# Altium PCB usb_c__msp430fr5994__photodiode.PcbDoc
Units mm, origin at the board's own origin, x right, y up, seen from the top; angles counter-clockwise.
Board outline 56 x 30 mm, 2 copper layers (Top, Bottom), stack 0 mm thick; 27 components, 18 nets, 155 pads, 48 vias.
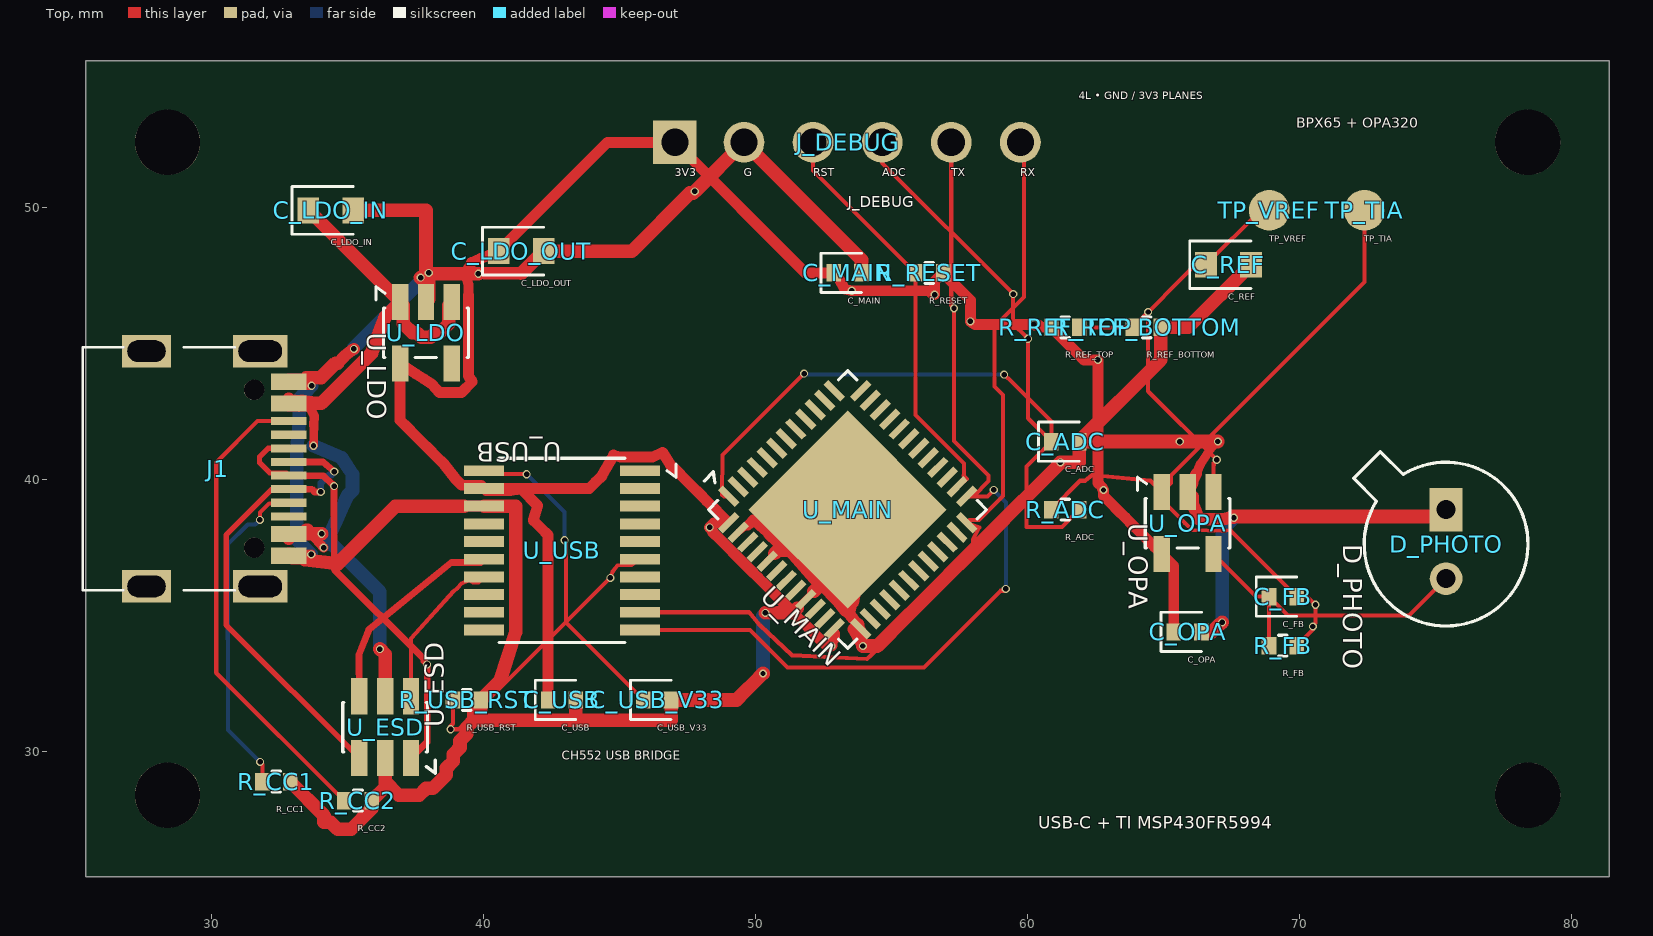
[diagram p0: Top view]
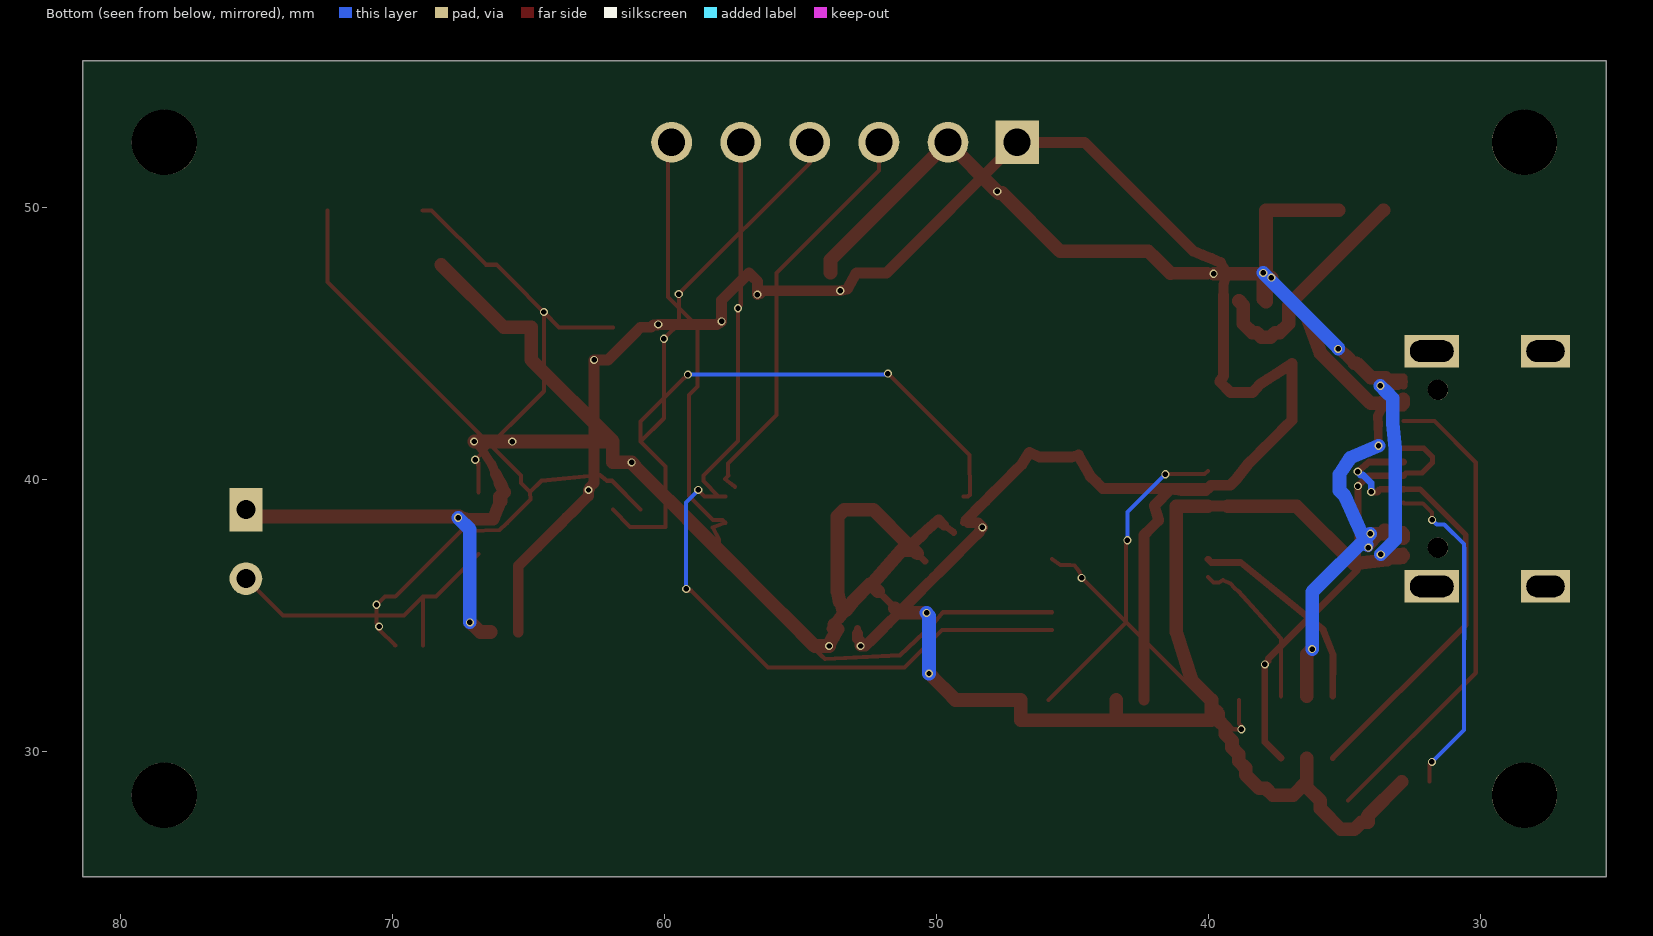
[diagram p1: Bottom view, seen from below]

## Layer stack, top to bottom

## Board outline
25.4,55.4 81.4,55.4 81.4,25.4 25.4,25.4

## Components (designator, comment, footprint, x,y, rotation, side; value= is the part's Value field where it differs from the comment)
C_ADC "" TSCIRCUIT-1.5600x0.6400mm 61.4,41.4 r0 top
C_FB "" TSCIRCUIT-1.5600x0.6400mm 69.4,35.7 r0 top
C_LDO_IN "" TSCIRCUIT-2.4500x0.9500mm 34.4,49.9 r0 top
C_LDO_OUT "" TSCIRCUIT-2.4500x0.9500mm 41.4,48.4 r0 top
C_MAIN "" TSCIRCUIT-1.5600x0.6400mm 53.4,47.6 r0 top
C_OPA "" TSCIRCUIT-1.5600x0.6400mm 65.9,34.4 r0 top
C_REF "" TSCIRCUIT-2.4500x0.9500mm 67.4,47.9 r0 top
C_USB "" TSCIRCUIT-1.5600x0.6400mm 42.9,31.9 r0 top
C_USB_V33 "" TSCIRCUIT-1.5600x0.6400mm 46.4,31.9 r0 top
D_PHOTO "" TSCIRCUIT-1.2000x3.9400mm 75.4,37.73 r270 top
J1 "" TSCIRCUIT-6.7732x9.8502mm 30.113,40.4 r90 top
J_DEBUG "" TSCIRCUIT-14.2000x1.5000mm 53.4,52.4 r0 top
R_ADC "" TSCIRCUIT-1.5600x0.6400mm 61.4,38.9 r0 top
R_CC1 "" TSCIRCUIT-1.5600x0.6400mm 32.4,28.9 r0 top
R_CC2 "" TSCIRCUIT-1.5600x0.6400mm 35.4,28.2 r0 top
R_FB "" TSCIRCUIT-1.5600x0.6400mm 69.4,33.9 r0 top
R_REF_BOTTOM "" TSCIRCUIT-1.5600x0.6400mm 64.4,45.6 r0 top
R_REF_TOP "" TSCIRCUIT-1.5600x0.6400mm 61.4,45.6 r0 top
R_RESET "" TSCIRCUIT-1.5600x0.6400mm 56.4,47.6 r0 top
R_USB_RST "" TSCIRCUIT-1.5600x0.6400mm 39.4,31.9 r0 top
TP_TIA "" TSCIRCUIT-1.5000x1.5000mm 72.4,49.9 r0 top
TP_VREF "" TSCIRCUIT-1.5000x1.5000mm 68.9,49.9 r0 top
U_ESD "" TSCIRCUIT-2.5000x3.6000mm#1 36.4,30.9 r90 top
U_LDO "" TSCIRCUIT-2.5000x3.6000mm#2 37.9,45.4 r270 top
U_MAIN "" TSCIRCUIT-9.5459x9.5459mm 53.4,38.9 r315 top
U_OPA "" TSCIRCUIT-2.5000x3.6000mm#2 65.9,38.4 r270 top
U_USB "" TSCIRCUIT-7.2000x6.2500mm 42.9,37.4 r180 top

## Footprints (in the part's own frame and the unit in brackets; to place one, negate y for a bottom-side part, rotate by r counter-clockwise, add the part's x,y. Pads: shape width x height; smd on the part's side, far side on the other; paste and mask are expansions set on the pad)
TSCIRCUIT-1.2000x3.9400mm [mm]
  rect 1.6x1.2 hole 0.7: 1(-1.17,0)
  round 1.2 hole 0.7: 2(1.37,0)
  silkscreen extent -3.3,-3.4 3.11,3.01
TSCIRCUIT-1.5000x1.5000mm [mm]
  round 1.5 smd: 1(0,0)
TSCIRCUIT-1.5600x0.6400mm [mm]
  rect 0.54x0.64 smd: 1(-0.51,0) 2(0.51,0)
  silkscreen extent -0.98,-0.72 0.51,0.72
TSCIRCUIT-2.4500x0.9500mm [mm]
  rect 0.8x0.95 smd: 1(-0.825,0) 2(0.825,0)
  silkscreen extent -1.43,-0.87 0.82,0.87
TSCIRCUIT-2.5000x3.6000mm#1 [mm]
  rect 1.325x0.6 smd: 1(-1.137,-0.95) 2(-1.137,0) 3(-1.137,0.95) 4(1.138,0.95) 5(1.138,0) 6(1.138,-0.95)
  silkscreen extent -1.69,-1.84 0.91,1.56
TSCIRCUIT-2.5000x3.6000mm#2 [mm]
  rect 1.325x0.6 smd: 1(-1.137,-0.95) 2(-1.137,0) 3(-1.137,0.95) 4(1.138,0.95) 5(1.138,-0.95)
  silkscreen extent -1.69,-1.84 0.91,1.56
TSCIRCUIT-6.7732x9.8502mm [mm]
  rect 1.2x2 hole 0.8 slot 1.6 at 90 deg: 1(-4.325,-1.693) 1(4.325,-1.693)
  rect 1.2x1.8 hole 0.8 slot 1.4 at 90 deg: 1(-4.325,2.487) 1(4.325,2.487)
  rect 0.3x1.3 smd: 1(-3.35,-2.737) 2(-3.05,-2.737) 3(-2.55,-2.737) 4(-2.25,-2.737) 5(-1.75,-2.737) 6(-1.25,-2.737) 7(-0.75,-2.737) 8(-0.25,-2.737) 9(0.25,-2.737) 10(0.75,-2.737) 11(1.25,-2.737) 12(1.75,-2.737) 13(2.55,-2.737) 14(2.25,-2.737) 15(3.35,-2.737) 16(3.05,-2.737)
  round 0.75 hole 0.75 unplated: NPTH-1(-2.9,-1.468) NPTH-2(2.9,-1.468)
  silkscreen extent -4.47,-0.75 4.47,4.83
TSCIRCUIT-7.2000x6.2500mm [mm]
  rect 1.475x0.4 smd: 1(-2.862,-2.925) 2(-2.862,-2.275) 3(-2.862,-1.625) 4(-2.862,-0.975) 5(-2.862,-0.325) 6(-2.862,0.325) 7(-2.862,0.975) 8(-2.862,1.625) 9(-2.862,2.275) 10(-2.862,2.925) 11(2.863,2.925) 12(2.863,2.275) 13(2.863,1.625) 14(2.863,0.975) 15(2.863,0.325) 16(2.863,-0.325) 17(2.863,-0.975) 18(2.863,-1.625) 19(2.863,-2.275) 20(2.863,-2.925)
  silkscreen extent -4.19,-3.39 2.31,3.38
TSCIRCUIT-9.5459x9.5459mm [mm]
  rect 0.875x0.25 smd: 1(-3.438,-2.75) 2(-3.438,-2.25) 3(-3.437,-1.75) 4(-3.437,-1.25) 5(-3.438,-0.75) 6(-3.438,-0.25) 7(-3.437,0.25) 8(-3.437,0.75) 9(-3.438,1.25) 10(-3.438,1.75) 11(-3.437,2.25) 12(-3.437,2.75) 25(3.438,2.75) 26(3.438,2.25) 27(3.438,1.75) 28(3.438,1.25) 29(3.438,0.75) 30(3.438,0.25) 31(3.438,-0.25) 32(3.438,-0.75) 33(3.438,-1.25) 34(3.438,-1.75) 35(3.438,-2.25) 36(3.438,-2.75)
  rect 0.25x0.875 smd: 13(-2.75,3.437) 14(-2.25,3.437) 15(-1.75,3.438) 16(-1.25,3.438) 17(-0.75,3.437) 18(-0.25,3.437) 19(0.25,3.438) 20(0.75,3.438) 21(1.25,3.437) 22(1.75,3.437) 23(2.25,3.438) 24(2.75,3.438) 37(2.75,-3.438) 38(2.25,-3.438) 39(1.75,-3.438) 40(1.25,-3.438) 41(0.75,-3.438) 42(0.25,-3.438) 43(-0.25,-3.438) 44(-0.75,-3.438) 45(-1.25,-3.438) 46(-1.75,-3.438) 47(-2.25,-3.438) 48(-2.75,-3.438)
  rect 5.15x5.15 smd: 49(0,0)
  silkscreen extent -4.47,-3.61 3.61,3.61
TSCIRCUIT-14.2000x1.5000mm [mm]
  rect 1.6x1.6 hole 1: 1(-6.35,0)
  round 1.5 hole 1: 2(-3.81,0) 3(-1.27,0) 4(1.27,0) 5(3.81,0) 6(6.35,0)

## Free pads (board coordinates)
  round 2.4 hole 2.4 unplated: NPTH-3(28.4,28.4) NPTH-4(78.4,52.4) NPTH-5(78.4,28.4) NPTH-6(28.4,52.4)

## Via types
v1: diameter 0.3, hole 0.2, Top to Bottom, 48 vias

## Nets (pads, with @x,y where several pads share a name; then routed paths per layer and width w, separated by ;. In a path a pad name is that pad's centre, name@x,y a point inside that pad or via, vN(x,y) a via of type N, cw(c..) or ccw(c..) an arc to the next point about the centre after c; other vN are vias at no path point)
ADC_IN: C_ADC.1 J_DEBUG.4 R_ADC.2 U_MAIN.1 | length 35.8
  Top w0.15: U_MAIN.1 48.855,39.386 48.788,39.441 48.793,40.9 v1(51.8,43.9) ; J_DEBUG.4 54.67,51.648 59.442,46.877 59.442,46.865 v1(59.487,46.82) 59.487,45.726 59.95,45.263 v1(60.034,45.179) 60.034,42.256 C_ADC.1 ; v1(59.153,43.862) 59.279,43.736 59.287,43.736 60.89,42.133 C_ADC.1 ; R_ADC.2 61.274,38.264 59.976,38.264 59.976,40.486 C_ADC.1
  Bottom w0.15: v1(51.8,43.9) 51.838,43.862 51.903,43.862 v1(59.153,43.862)
GND: C_ADC.2 C_LDO_IN.2 C_LDO_OUT.2 C_MAIN.2 C_OPA.2 C_REF.2 C_USB.2 C_USB_V33.2 D_PHOTO.1 J1.1@32.849,37.05 J1.2 J1.15 J1.16 J_DEBUG.2 R_CC1.2 R_CC2.2 R_REF_BOTTOM.2 R_USB_RST.2 U_ESD.2 U_LDO.2 U_MAIN.36 U_MAIN.40 U_MAIN.44 U_MAIN.47 U_MAIN.49 U_OPA.2 U_USB.18 | length 156.9
  Top w0.25: U_MAIN.47 49.735,38.323 ; U_MAIN.40@51.544,35.276 U_MAIN.40 ; U_MAIN.40 52.163,35.895 U_MAIN.40 ; U_MAIN.44 50.748,37.309 U_MAIN.44
  Top w0.251: U_MAIN.44 U_MAIN.44@50.716,37.278
  Top w0.288: J1.16@32.849,43.6 J1.16 32.946,43.468 J1.16@33.037,43.45
  Top w0.3: J1.1@32.849,37.05 32.849,37.2 J1.2 ; J1.16@32.849,43.6 J1.15 33.499,43.75 ; J1.2@32.864,37.323 J1.2 ; J1.1@32.911,37.2 J1.2 ; J1.16@33.13,43.45 33.224,43.45 v1(33.697,43.449)
  Top w0.301: J1.16@33.037,43.45 J1.16@33.13,43.45
  Top w0.325: J1.1@32.911,37.2 J1.1@32.975,37.043 ; v1(39.828,47.571) 39.845,47.588 40.062,47.588 ; 66.369,40.556 66.552,40.841 66.734,41.125 v1(67.013,41.401)
  Top w0.335: J1.1@32.975,37.043 J1.1@33.454,37.056
  Top w0.344: U_MAIN.36@53.613,34.865 U_MAIN.36
  Top w0.35: J1.2@32.864,37.323 33.274,37.288 v1(33.684,37.254) ; 66.212,40.217 66.369,40.556
  Top w0.375: 49.735,38.323 49.758,38.34 49.931,38.525
  Top w0.382: 53.627,34.884 U_MAIN.36@53.775,34.681
  Top w0.4: U_USB.18@39.3,39.025 U_USB.18 ; 49.931,38.525 50.143,38.342 50.355,38.158 50.546,37.963 ; 53.341,35.206 U_MAIN.36@53.613,34.865 ; U_MAIN.49@53.565,35.487 53.478,35.087 53.627,34.884
  Top w0.425: U_OPA.2@66.056,39.877 66.212,40.217
  Top w0.437: 34.652,44.284 34.914,44.546 v1(35.251,44.808) ; 50.546,37.963 50.77,37.759 50.994,37.556
  Top w0.45: 40.062,47.588 40.512,47.588 40.962,47.588 41.413,47.588 ; U_OPA.2@66.035,39.205 66.171,38.873 66.306,38.541 ; U_OPA.2@66.072,39.169 66.189,38.855 66.306,38.541 ; v1@67.567,38.645 67.181,38.541 ; v1(67.6,38.6) 67.181,38.541 ; 66.306,38.541 66.744,38.541 ; 66.306,38.541 66.744,38.541 ; 66.744,38.541 67.181,38.541 ; 66.744,38.541 67.181,38.541
  Top w0.475: U_MAIN.44@50.716,37.278 50.994,37.556 ; 53.651,34.506 U_MAIN.36@53.775,34.681 ; U_OPA.2 U_OPA.2@66.056,39.877
  Top w0.5: R_CC1.2 32.91,28.89 34.15,27.65 34.15,27.4 34.4,27.4 34.65,27.15 35.15,27.15 35.9,27.9 35.9,28.19 R_CC2.2 36.4,28.69 U_ESD.2 36.4,28.9 36.9,28.4 37.65,28.4 37.9,28.65 38.15,28.65 38.65,29.15 38.65,29.4 38.9,29.65 38.9,29.9 39.15,30.15 39.15,30.4 39.4,30.65 39.4,30.9 39.65,31.15 39.65,31.4 39.9,31.65 39.9,31.9 R_USB_RST.2 ; J1.1@33.454,37.056 34.65,36.9 36.775,39.025 U_USB.18@39.3,39.025 ; 33.499,43.75 34.044,43.75 34.577,44.284 34.652,44.284 ; C_LDO_IN.2 37.9,49.9 U_LDO.2 ; v1(38,47.6) U_LDO.2@38,46.637 ; v1(39.828,47.571) 39.399,47.571 38.969,47.571 38.54,47.571 38.11,47.571 38.088,47.593 38.007,47.593 v1(37.7,47.425) 38,47.119 U_LDO.2@38,46.637 ; U_USB.18 41.2,39.025 41.2,34.4 40.614,32.598 40.262,32.249 R_USB_RST.2 ; 41.413,47.588 41.683,47.858 41.954,48.129 C_LDO_OUT.2 45.469,48.4 47.605,50.536 47.723,50.536 v1(47.782,50.595) 47.785,50.595 J_DEBUG.2 53.91,48.08 C_MAIN.2 ; v1(50.289,32.874) 50.266,32.851 49.949,32.534 49.632,32.217 49.315,31.9 48.834,31.9 48.353,31.9 47.872,31.9 47.391,31.9 C_USB_V33.2 46.91,31.15 43.41,31.15 ; v1(50.38,35.1) 51.368,35.1 51.544,35.276 ; 53.341,35.206 53.068,35.546 52.464,36.15 52.4,36.15 52.4,36.132 52.163,35.895 52.317,36.049 52.317,36.233 51.317,37.4 50.839,37.4 50.748,37.309 51.049,37.61 52.339,38.9 U_MAIN.49 53.654,38.645 53.654,38.185 53.654,37.725 53.653,37.265 53.653,36.805 53.653,36.346 53.652,35.886 U_MAIN.49@53.565,35.487 ; 53.651,34.506 53.816,34.205 53.981,33.904 v1(53.961,33.884) 54.229,33.884 54.496,33.884 54.844,34.232 55.191,34.579 55.539,34.927 55.887,35.275 56.234,35.622 56.582,35.97 56.93,36.318 57.278,36.666 57.625,37.013 57.973,37.361 58.321,37.709 58.668,38.056 59.016,38.404 59.364,38.752 59.711,39.099 60.059,39.447 60.407,39.795 60.754,40.142 61.102,40.49 61.102,40.515 v1(61.222,40.635) 61.91,40.635 C_ADC.2 ; U_OPA.2@66.035,39.205 66.035,39.402 U_OPA.2 66.072,39.366 U_OPA.2@66.072,39.169 ; C_OPA.2 66.788,34.4 67.051,34.663 67.078,34.663 v1(67.165,34.75) ; v1(67.013,41.401) 67.011,41.4 v1(65.609,41.4) 65.41,41.4 64.91,41.4 64.41,41.4 63.91,41.4 63.41,41.4 62.91,41.4 62.41,41.4 C_ADC.2 ; v1@67.567,38.645 68.041,38.645 68.514,38.645 68.988,38.645 69.461,38.645 69.935,38.645 70.409,38.645 70.882,38.645 71.356,38.645 71.83,38.645 72.303,38.645 72.777,38.645 73.25,38.645 73.724,38.645 74.198,38.645 74.671,38.645 75.145,38.645 D_PHOTO.1 ; C_REF.2 65.925,45.6 R_REF_BOTTOM.2 64.91,44.4 C_ADC.2 ; U_LDO.2 U_LDO.2@38,46.637 ; U_LDO.2 U_LDO.2@38,46.637 ; R_USB_RST.2 39.91,31.15 43.41,31.15 ; 43.41,31.15 C_USB.2 43.41,31.15
  Bottom w0.5: v1(33.684,37.254) 33.15,37.787 33.15,41.15 33.243,42.073 33.243,42.534 33.243,42.995 33.47,43.222 v1(33.697,43.449) ; v1(35.251,44.808) 35.251,44.851 v1(38,47.6) ; v1(50.289,32.874) 50.289,33.298 50.289,33.722 50.289,34.147 50.289,34.571 50.289,34.995 50.379,35.085 50.379,35.099 v1(50.38,35.1) ; v1(67.165,34.75) 67.165,38.165 v1(67.6,38.6)
MAIN_RESET: J_DEBUG.3 R_RESET.1 U_MAIN.23 | length 15.2
  Top w0.15: J_DEBUG.3 52.13,51.36 R_RESET.1 55.89,42.382 57.68,40.592 57.68,40.182 57.656,40.147 57.793,40.026 U_MAIN.23
PD_SUM: C_FB.1 D_PHOTO.2 R_FB.1 U_OPA.4 | length 11.9
  Top w0.15: U_OPA.4 68.412,35.7 C_FB.1 ; R_FB.1 C_FB.1 ; D_PHOTO.2 74.04,35 69.6,35 69.59,35 C_FB.1
TIA_OUT: C_FB.2 R_ADC.1 R_FB.2 TP_TIA.1 U_OPA.1 | length 27.5
  Top w0.15: R_ADC.1 61.949,39.959 62.125,39.959 62.4,40.175 64.529,39.959 U_OPA.1 ; R_FB.2 70.506,34.496 v1(70.506,34.6) 70.539,34.633 70.539,34.676 70.6,34.737 v1(70.6,35.4) 70.56,35.44 70.552,35.44 70.292,35.7 C_FB.2 67.465,38.145 67.186,38.119 66.072,38.145 65.813,38.391 64.946,39.263 U_OPA.1 ; TP_TIA.1 72.399,47.266 65.281,40.151 65.283,39.87 U_OPA.1
UART_MAIN_RX: J_DEBUG.6 U_MAIN.25 U_USB.9 | length 31.4
  Top w0.15: U_USB.9 49.78,35.125 50.175,34.645 51.358,33.544 54.11,33.4 54.259,33.544 58.007,37.295 58.01,37.795 58.245,38.241 U_MAIN.25 57.88,38.519 58.231,38.519 59.11,39.398 59.113,39.55 59.11,43.108 58.798,43.42 58.798,45.627 59.889,46.717 59.889,52.261 J_DEBUG.6
UART_MAIN_TX: J_DEBUG.5 U_MAIN.24 U_USB.10 | length 34.2
  Top w0.15: U_USB.10 49.81,34.475 51.191,33.095 56.202,33.095 59.022,35.914 59.147,35.914 v1(59.215,35.982) ; J_DEBUG.5 57.21,46.412 57.218,46.403 57.218,46.393 v1(57.311,46.3) 57.311,41.415 58.58,40.146 58.58,39.942 58.024,39.386 U_MAIN.24 58.54,39.386 v1(58.773,39.623)
  Bottom w0.15: v1(58.773,39.623) 58.814,39.586 58.814,39.564 59.215,39.163 v1(59.215,35.982)
USB_BRIDGE_RESET: R_USB_RST.1 U_USB.6 | length 10.7
  Top w0.15: R_USB_RST.1 38.89,31.026 38.801,30.937 38.801,30.83 v1(38.806,30.825) 39.117,30.825 44.651,36.359 v1(44.68,36.388) 44.68,36.432 44.763,36.624 44.939,36.848 45.113,36.863 45.106,36.86 45.439,36.86 U_USB.6
USB_BRIDGE_V33: C_USB_V33.1 U_USB.20 | length 11.7
  Top w0.15: U_USB.20 40.163,40.2 v1(41.6,40.2) ; v1(42.996,37.772) 43.043,37.725 43.043,37.72 43.043,34.747 C_USB_V33.1
  Bottom w0.15: v1(41.6,40.2) 41.606,40.194 42.996,38.804 v1(42.996,37.772)
USB_CC1: J1.6 R_CC1.1 | length 12.3
  Top w0.15: v1(31.796,38.521) 31.796,38.786 32.137,39.127 32.826,39.127 J1.6 ; v1(31.8,29.621) 31.8,29.612 31.89,29.522 R_CC1.1
  Bottom w0.15: v1(31.796,38.521) 31.779,38.504 31.623,38.348 31.348,38.348 30.629,37.629 30.612,37.397 30.624,30.792 v1(31.8,29.621)
USB_CC2: J1.12 R_CC2.1 | length 17.7
  Top w0.15: J1.12 31.706,42.15 30.19,40.634 30.19,32.9 R_CC2.1
USB_DM_MCU: U_ESD.4 U_USB.15 | length 7.7
  Top w0.25: U_ESD.4 35.436,33.576 35.809,34.503 38.837,36.954 39.914,36.952 U_USB.15
USB_DM_PORT: J1.7 J1.9 U_ESD.3 | length 17.3
  Top w0.2: J1.7 32.243,39.65 30.551,37.957 30.551,34.661 U_ESD.3
  Top w0.25: J1.7 33.703,39.65 33.806,39.547 v1(34.034,39.548) v1(34.034,39.548) ; J1.9 34.113,40.65 v1(34.527,40.296)
  Bottom w0.25: v1(34.034,39.548) 34.034,39.874 34.333,40.173 34.426,40.173 v1(34.527,40.296)
USB_DP_MCU: U_ESD.6 U_USB.14 | length 5.8
  Top w0.15: U_ESD.6 37.35,34.16 38.92,35.904 39.061,36.011 39.206,36.18 39.487,36.304 39.622,36.224 39.836,36.224 U_USB.14
USB_DP_PORT: J1.8 J1.10 U_ESD.1 | length 16.2
  Top w0.2: J1.8 32.755,40.244 32.163,40.244 31.781,40.626 31.781,40.835 32.096,41.15 J1.10
  Top w0.25: J1.8 34.129,40.138 34.458,39.82 34.476,39.827 v1(34.522,39.762) 34.526,36.702 37.819,33.402 37.819,33.334 v1(37.943,33.21) 37.943,30.355 U_ESD.1
VBUS5: C_LDO_IN.1 J1.3 J1.4 J1.13 J1.14 U_ESD.5 U_LDO.1 U_LDO.3 | length 32.2
  Top w0.3: J1.3 J1.3@32.946,37.868 ; J1.3@32.849,38 J1.4 33.202,38.15 33.499,38.15 ; J1.14@32.849,42.8 J1.14 J1.14@33.242,42.658 ; J1.3@33.037,37.85 33.13,37.85 33.224,37.85 33.386,38.012 33.499,38.012
  Top w0.301: J1.3@32.946,37.868 J1.3@33.037,37.85
  Top w0.325: v1(33.764,41.245) 33.773,41.614 33.782,41.984
  Top w0.326: J1.14@33.242,42.658 33.634,42.666
  Top w0.35: 33.554,38.15 33.844,37.826 v1(34.135,37.502) ; 33.634,42.666 33.791,42.353 33.782,41.984
  Top w0.45: J1.13 J1.13@33.335,42.878
  Top w0.475: 33.499,38.15 33.554,38.15
  Top w0.5: J1.3 J1.3@32.849,38 ; J1.13@32.849,42.8 J1.13@32.849,42.95 ; J1.13@33.335,42.878 33.822,42.806 34.056,42.806 35.9,44.65 36.405,45.992 U_LDO.1 ; 33.499,38.012 v1(34.061,38.012) ; C_LDO_IN.1 33.587,49.9 U_LDO.1 ; v1(36.205,33.772) 36.4,33.577 U_ESD.5 ; U_LDO.3 38.879,46.567 38.9,46.567 38.733,46.4 38.733,45.733 38.4,45.4 38.233,45.4 38.067,45.233 37.733,45.233 37.567,45.4 37.4,45.4 37.067,45.733 37.067,46.4 36.95,46.517 U_LDO.1
  Bottom w0.325: v1(34.135,37.502) v1@34.2,37.6
  Bottom w0.5: v1(33.764,41.245) 34.8,40.8 35.2,40.2 35.2,39.6 35,39.4 34.8,38.95 34.6,38.5 34.4,38.05 v1@34.2,37.6 ; v1(34.061,38.012) 36.205,35.868 v1(36.205,33.772)
VCC_3V3: C_LDO_OUT.1 C_MAIN.1 C_OPA.1 C_USB.1 J_DEBUG.1 R_REF_TOP.1 R_RESET.2 U_LDO.5 U_MAIN.37 U_MAIN.48 U_OPA.5 U_USB.19 | length 82.9
  Top w0.25: U_MAIN.48@48.848,38.414 U_MAIN.48 U_MAIN.48@48.936,38.502 ; 52.914,34.348 U_MAIN.37
  Top w0.35: 39.4,47.4 39.342,47.633 39.458,47.808 39.575,47.983
  Top w0.375: 39.4,47.4 39.458,47.167 39.458,46.793
  Top w0.4: 39.458,46.793 39.458,46.42 39.458,46.047 39.458,45.673 39.458,45.3 39.458,44.927 39.458,44.553 39.458,44.18 39.458,43.807 39.6,43.6 39.2,43.2 38.4,43.2 38.117,43.506 37.825,43.695 37.533,43.884 37.242,44.073 U_LDO.5 36.95,43.916 36.95,43.569 36.95,43.222 36.95,42.876 36.95,42.529 36.95,42.182 37.215,41.917 37.481,41.652 37.746,41.387 38.011,41.121 38.276,40.856 38.542,40.591 39,40 39.2,39.8 39.338,39.795 39.628,39.795 39.918,39.795 U_USB.19 ; 39.575,47.983 39.908,48.122 40.242,48.261 C_LDO_OUT.1 44.575,52.4 J_DEBUG.1 51.85,47.6 C_MAIN.1 52.961,47.6 53.3,47 v1(53.554,46.943) 53.909,46.943 54.264,46.943 54.619,46.943 54.974,46.943 55.33,46.943 55.685,46.943 56.04,46.943 56.395,46.943 56.507,46.831 56.569,46.831 v1(56.6,46.8) 56.6,47.045 56.6,47.29 56.755,47.445 R_RESET.2 57.915,46.595 v1(57.915,45.816) 57.964,45.767 58.019,45.767 58.078,45.708 v1(60.243,45.708) 60.269,45.682 60.424,45.682 60.506,45.6 R_REF_TOP.1 61.13,45.36 61.37,45.12 61.61,44.88 61.851,44.639 62.091,44.399 62.393,44.399 v1@62.599,44.399 ; C_USB.1 42.39,32.279 42.39,32.657 42.39,33.036 42.39,33.415 42.39,33.793 42.39,34.172 42.39,34.551 42.39,34.929 42.39,35.308 42.39,35.687 42.39,36.065 42.39,36.444 42.39,36.823 42.39,37.201 42.39,37.58 42.39,37.959 42.117,38.232 41.845,38.504 42,39.05 41.4,39.65 41,39.6 40.436,39.595 40.118,39.595 U_USB.19 ; U_MAIN.48@48.848,38.414 48.759,38.414 48.494,38.414 v1(48.326,38.246) 48.437,38.135 48.437,38.074 48.717,37.794 48.996,37.515 49.276,37.235 49.556,36.955 49.835,36.676 50.115,36.396 50.395,36.116 50.674,35.837 50.954,35.557 51.234,35.277 51.513,34.998 51.793,34.718 52.073,34.438 52.352,34.159 52.632,33.879 v1(52.803,33.884) 52.825,33.901 52.825,34.062 52.914,34.151 52.914,34.348 ; 48.936,38.502 48.756,38.682 48.488,38.951 48.219,39.22 47.95,39.488 47.682,39.757 47.413,40.025 47.145,40.294 46.876,40.563 46.6,41 46.22,40.831 45.833,40.831 45.446,40.831 45.059,40.831 44.8,40.9 44.365,40.137 44.134,39.906 43.902,39.675 43.516,39.675 43.129,39.675 42.743,39.675 42.356,39.675 41.97,39.675 41.583,39.675 41.197,39.675 40.81,39.675 40.424,39.675 U_USB.19 ; v1(62.6,44.4) 62.6,44.023 62.6,43.647 62.6,43.27 62.6,42.893 62.6,42.517 62.6,42.14 62.6,41.763 62.6,41.387 62.6,41.01 62.6,40.633 62.6,40.257 62.6,39.88 62.762,39.718 62.762,39.665 v1(62.807,39.619) 62.807,39.405 63.075,39.137 63.343,38.869 63.611,38.602 63.879,38.334 64.146,38.066 64.414,37.798 64.682,37.53 U_OPA.5 65.39,36.822 C_OPA.1
VREF_0V5: C_REF.1 R_REF_BOTTOM.1 R_REF_TOP.2 TP_VREF.1 U_OPA.3 | length 17.3
  Top w0.15: R_REF_TOP.2 R_REF_BOTTOM.1 ; U_OPA.3 66.85,40.522 66.861,40.533 66.861,40.618 v1(66.971,40.728) 64.45,43.249 64.45,45.96 64.45,46.159 v1(64.447,46.162) 64.447,46.157 R_REF_BOTTOM.1 ; TP_VREF.1 68.575,49.9 C_REF.1 66.19,47.9 R_REF_BOTTOM.1
pads on no net: J1.1@27.626,36.075 J1.1@27.626,44.725 J1.1@31.806,36.075 J1.1@31.806,44.725 J1.5 J1.11 J1.NPTH-1 J1.NPTH-2 U_LDO.4 U_MAIN.2 U_MAIN.3 U_MAIN.4 U_MAIN.5 U_MAIN.6 U_MAIN.7 U_MAIN.8 U_MAIN.9 U_MAIN.10 U_MAIN.11 U_MAIN.12 U_MAIN.13 U_MAIN.14 U_MAIN.15 U_MAIN.16 U_MAIN.17 U_MAIN.18 U_MAIN.19 U_MAIN.20 U_MAIN.21 U_MAIN.22 U_MAIN.26 U_MAIN.27 U_MAIN.28 U_MAIN.29 U_MAIN.30 U_MAIN.31 U_MAIN.32 U_MAIN.33 U_MAIN.34 U_MAIN.35 U_MAIN.38 U_MAIN.39 U_MAIN.41 U_MAIN.42 U_MAIN.43 U_MAIN.45 U_MAIN.46 U_USB.1 U_USB.2 U_USB.3 U_USB.4 U_USB.5 U_USB.7 U_USB.8 U_USB.11 U_USB.12 U_USB.13 U_USB.16 U_USB.17

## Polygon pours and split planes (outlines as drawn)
GND on Mid1 (solid): 81.1,55.1 25.7,55.1 25.7,25.7 81.1,25.7
VCC_3V3 on Mid2 (solid): 81.1,55.1 25.7,55.1 25.7,25.7 81.1,25.7

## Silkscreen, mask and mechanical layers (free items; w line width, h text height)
Top Overlay:
  text "4L • GND / 3V3 PLANES" at 61.9,53.9 h0.48
  text "BPX65 + OPA320" at 69.9,52.8 h0.65
  text "CH552 USB BRIDGE" at 42.9,29.6 h0.55
  text "USB-C + TI MSP430FR5994" at 60.4,27 h0.78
